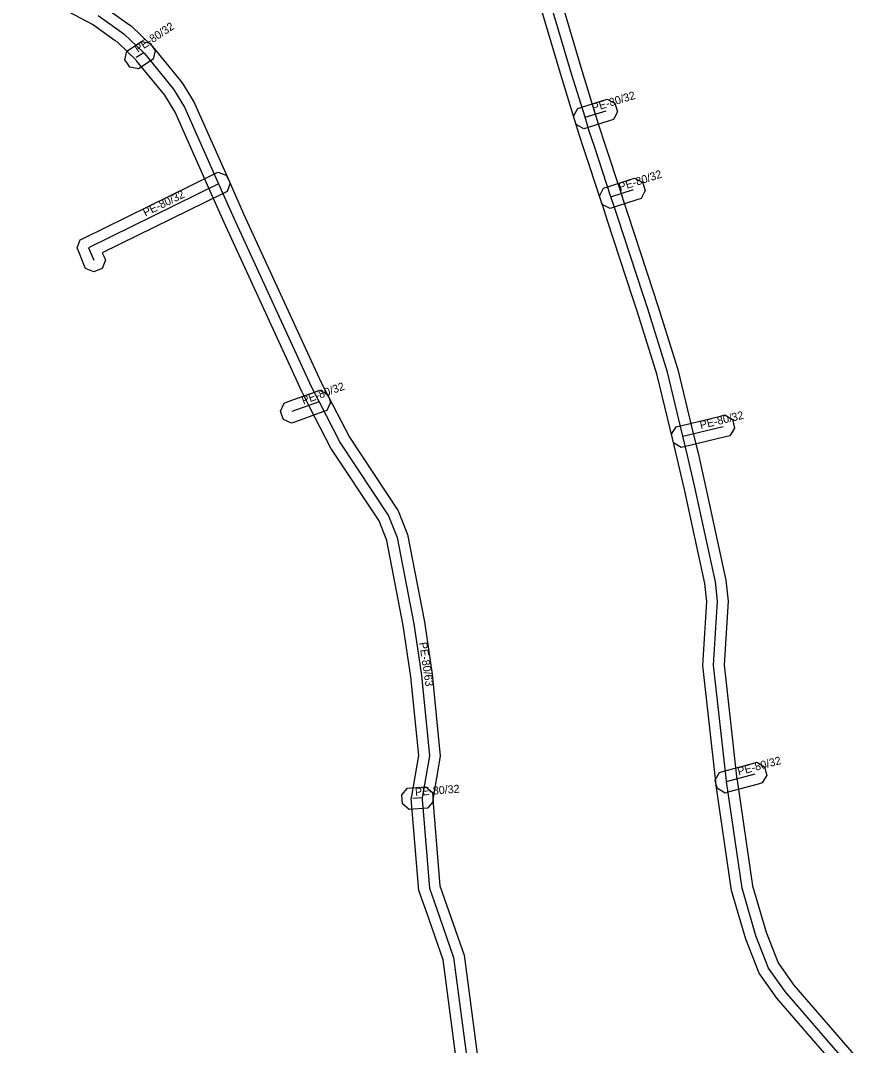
# Model space of a CAD drawing. Extents: x -569373 to -565022, y -1135090 to -1131496.
# Drawn here: x -568895.5 to -568815.6, y -1133085.8 to -1132989.8 of the extents above; entities that cross this region are included whole.
import ezdxf

# ---------------------------------------------------------------- set-up
doc = ezdxf.new("R2010")
doc.units = 0
for name, color, linetype in [('1', 7, 'Continuous'), ('24', 7, 'Continuous'), ('30', 7, 'Continuous')]:
    doc.layers.add(name, color=color, linetype=linetype)

msp = doc.modelspace()

# ---------------------------------------------------------------- linework, layer by layer
at = {"layer": '1'}
for points in [[(-568845.843, -1132984.667), (-568842.933, -1132994.501), (-568841.674, -1132998.576), (-568841.277, -1132999.877), (-568840.81, -1133001.287), (-568839.251, -1133006.026), (-568839.081, -1133006.536), (-568838.614, -1133007.96), (-568836.276, -1133015.098), (-568835.808, -1133016.525), (-568833.946, -1133022.493), (-568832.488, -1133028.505), (-568832.047, -1133030.341), (-568831.364, -1133033.302), (-568829.431, -1133042.222), (-568829.227, -1133044.189), (-568829.597, -1133050.165), (-568828.397, -1133060.902), (-568828.389, -1133060.966), (-568826.941, -1133070.867), (-568825.673, -1133075.217), (-568824.543, -1133078.093), (-568823.101, -1133080.143), (-568815.608, -1133088.794)], [(-568817.152, -1133090.066), (-568824.679, -1133081.377), (-568826.317, -1133079.047), (-568827.567, -1133075.863), (-568828.899, -1133071.293), (-568830.371, -1133061.234), (-568830.383, -1133061.138), (-568831.603, -1133050.215), (-568831.233, -1133044.231), (-568831.409, -1133042.538), (-568833.316, -1133033.738), (-568833.993, -1133030.799), (-568834.432, -1133028.975), (-568835.874, -1133023.027), (-568837.712, -1133017.135), (-568838.176, -1133015.72), (-568840.514, -1133008.582), (-568840.979, -1133007.164), (-568841.149, -1133006.654), (-568842.71, -1133001.913), (-568843.183, -1133000.483), (-568843.586, -1132999.164), (-568844.847, -1132995.079), (-568847.737, -1132985.313)], [(-568854.172, -1133091.14), (-568855.918, -1133077.812), (-568857.494, -1133073.3), (-568858.196, -1133071.289), (-568858.906, -1133062.715), (-568858.867, -1133062.459), (-568858.209, -1133058.644), (-568858.943, -1133051.293), (-568859.656, -1133046.479), (-568861.204, -1133038.519), (-568861.923, -1133036.673), (-568866.433, -1133029.867), (-568868.439, -1133025.987), (-568869.16, -1133024.576), (-568876.441, -1133008.732), (-568877.874, -1133005.517), (-568881.038, -1132998.404), (-568881.999, -1132996.818), (-568884.643, -1132993.582), (-568884.687, -1132993.537), (-568884.69, -1132993.534), (-568886.438, -1132991.854), (-568886.649, -1132991.705), (-568888.759, -1132990.191), (-568895.52, -1132986.587)], [(-568887.701, -1132988.489), (-568885.491, -1132990.075), (-568885.162, -1132990.306), (-568883.29, -1132992.106), (-568883.273, -1132992.123), (-568883.157, -1132992.238), (-568880.361, -1132995.662), (-568879.262, -1132997.476), (-568876.046, -1133004.703), (-568874.619, -1133007.908), (-568867.36, -1133023.704), (-568866.661, -1133025.073), (-568864.707, -1133028.853), (-568860.137, -1133035.747), (-568859.276, -1133037.961), (-568857.684, -1133046.141), (-568856.957, -1133051.047), (-568856.191, -1133058.716), (-568856.893, -1133062.781), (-568856.894, -1133062.785), (-568856.224, -1133070.871), (-568855.606, -1133072.64), (-568853.962, -1133077.348), (-568852.188, -1133090.88)]]:
    msp.add_lwpolyline(points, dxfattribs=at)
for points in [[(-568883.08, -1132993.432), (-568883.425, -1132993.662), (-568884.115, -1132994.122), (-568884.46, -1132994.352), (-568885.272, -1132994.19), (-568885.502, -1132993.845), (-568885.732, -1132993.5), (-568885.57, -1132992.688), (-568885.225, -1132992.458), (-568884.535, -1132991.998), (-568884.19, -1132991.768), (-568883.378, -1132991.93), (-568883.148, -1132992.275), (-568882.918, -1132992.62)], [(-568843.322, -1132998.038), (-568842.926, -1132997.915), (-568840.956, -1132997.305), (-568840.56, -1132997.182), (-568839.828, -1132997.568), (-568839.705, -1132997.964), (-568839.582, -1132998.36), (-568839.968, -1132999.092), (-568840.364, -1132999.215), (-568842.334, -1132999.825), (-568842.73, -1132999.948), (-568843.462, -1132999.562), (-568843.585, -1132999.166), (-568843.708, -1132998.77)], [(-568876.147, -1133005.825), (-568876.519, -1133006.008), (-568887.856, -1133011.574), (-568887.726, -1133011.886), (-568887.567, -1133012.269), (-568887.884, -1133013.035), (-568888.266, -1133013.194), (-568888.649, -1133013.353), (-568889.415, -1133013.036), (-568889.574, -1133012.654), (-568890.064, -1133011.474), (-568890.216, -1133011.108), (-568889.936, -1133010.367), (-568889.581, -1133010.192), (-568877.401, -1133004.212), (-568877.029, -1133004.03), (-568876.245, -1133004.297), (-568876.062, -1133004.669), (-568875.88, -1133005.041)], [(-568840.903, -1133005.517), (-568840.509, -1133005.389), (-568838.389, -1133004.699), (-568837.995, -1133004.571), (-568837.257, -1133004.947), (-568837.129, -1133005.341), (-568837.001, -1133005.735), (-568837.377, -1133006.473), (-568837.771, -1133006.601), (-568839.891, -1133007.291), (-568840.285, -1133007.419), (-568841.023, -1133007.043), (-568841.151, -1133006.649), (-568841.279, -1133006.255)], [(-568866.82, -1133026.329), (-568867.209, -1133026.47), (-568869.749, -1133027.39), (-568870.139, -1133027.531), (-568870.889, -1133027.18), (-568871.03, -1133026.791), (-568871.171, -1133026.401), (-568870.82, -1133025.651), (-568870.431, -1133025.51), (-568867.891, -1133024.59), (-568867.501, -1133024.449), (-568866.751, -1133024.8), (-568866.61, -1133025.189), (-568866.469, -1133025.579)], [(-568834.098, -1133027.865), (-568833.695, -1133027.768), (-568829.935, -1133026.858), (-568829.532, -1133026.761), (-568828.825, -1133027.192), (-568828.728, -1133027.595), (-568828.631, -1133027.998), (-568829.062, -1133028.705), (-568829.465, -1133028.802), (-568833.225, -1133029.712), (-568833.628, -1133029.809), (-568834.335, -1133029.378), (-568834.432, -1133028.975), (-568834.529, -1133028.572)], [(-568830.042, -1133060.244), (-568829.642, -1133060.135), (-568826.952, -1133059.405), (-568826.552, -1133059.296), (-568825.834, -1133059.708), (-568825.725, -1133060.108), (-568825.616, -1133060.508), (-568826.028, -1133061.226), (-568826.428, -1133061.335), (-568829.118, -1133062.065), (-568829.518, -1133062.174), (-568830.236, -1133061.762), (-568830.345, -1133061.362), (-568830.454, -1133060.962)], [(-568857.389, -1133063.585), (-568857.802, -1133063.617), (-568858.702, -1133063.687), (-568859.115, -1133063.719), (-568859.745, -1133063.181), (-568859.777, -1133062.768), (-568859.809, -1133062.355), (-568859.271, -1133061.725), (-568858.858, -1133061.693), (-568857.958, -1133061.623), (-568857.545, -1133061.591), (-568856.915, -1133062.129), (-568856.883, -1133062.542), (-568856.851, -1133062.955)]]:
    msp.add_lwpolyline(points, close=True, dxfattribs=at)
at = {"layer": '24'}
for points in [[(-568816.38, -1133089.43), (-568823.89, -1133080.76), (-568825.43, -1133078.57), (-568826.62, -1133075.54), (-568827.92, -1133071.08), (-568829.38, -1133061.1), (-568829.39, -1133061.02), (-568830.6, -1133050.19), (-568830.23, -1133044.21), (-568830.42, -1133042.38), (-568832.34, -1133033.52), (-568833.02, -1133030.57), (-568833.46, -1133028.74), (-568834.91, -1133022.76), (-568836.76, -1133016.83), (-568837.226, -1133015.409), (-568839.564, -1133008.271), (-568840.03, -1133006.85), (-568840.2, -1133006.34), (-568841.76, -1133001.6), (-568842.23, -1133000.18), (-568842.63, -1132998.87), (-568843.89, -1132994.79), (-568846.79, -1132984.99)], [(-568888.23, -1132989.34), (-568886.07, -1132990.89), (-568885.8, -1132991.08), (-568883.99, -1132992.82), (-568883.98, -1132992.83), (-568883.9, -1132992.91), (-568881.18, -1132996.24), (-568880.15, -1132997.94), (-568876.96, -1133005.11), (-568875.53, -1133008.32), (-568868.26, -1133024.14), (-568867.55, -1133025.53), (-568865.57, -1133029.36), (-568861.03, -1133036.21), (-568860.24, -1133038.24), (-568858.67, -1133046.31), (-568857.95, -1133051.17), (-568857.2, -1133058.68), (-568857.88, -1133062.62), (-568857.9, -1133062.75), (-568857.21, -1133071.08), (-568856.55, -1133072.97), (-568854.94, -1133077.58), (-568853.18, -1133091.01)], [(-568883.98, -1132992.83), (-568884.67, -1132993.29)], [(-568842.63, -1132998.87), (-568840.66, -1132998.26)], [(-568876.96, -1133005.11), (-568889.14, -1133011.09), (-568888.65, -1133012.27)], [(-568840.2, -1133006.34), (-568838.08, -1133005.65)], [(-568867.55, -1133025.53), (-568870.09, -1133026.45)], [(-568833.46, -1133028.74), (-568829.7, -1133027.83)], [(-568829.38, -1133061.1), (-568826.69, -1133060.37)], [(-568857.88, -1133062.62), (-568858.78, -1133062.69)]]:
    msp.add_lwpolyline(points, dxfattribs=at)

# ---------------------------------------------------------------- texts
at = {"layer": '30'}
for s, rotation, p in [('PE-80/32', 33.69007, (-568884.525, -1132992.86)), ('PE-80/32', 17.20486, (-568841.845, -1132998.365)), ('PE-80/32', 18.0286, (-568839.34, -1133005.795)), ('PE-80/32', 26.1496, (-568883.823, -1133008.182)), ('PE-80/32', 19.91063, (-568869.02, -1133025.79)), ('PE-80/32', 13.60519, (-568831.78, -1133028.085)), ('PE-80/63', 278.42697, (-568858.176, -1133048.093)), ('PE-80/32', 15.183, (-568828.235, -1133060.535)), ('PE-80/32', 4.44738, (-568858.53, -1133062.455))]:
    msp.add_text(s, height=0.75, rotation=rotation, dxfattribs=at).set_placement(p)

doc.saveas('drawing.dxf')
